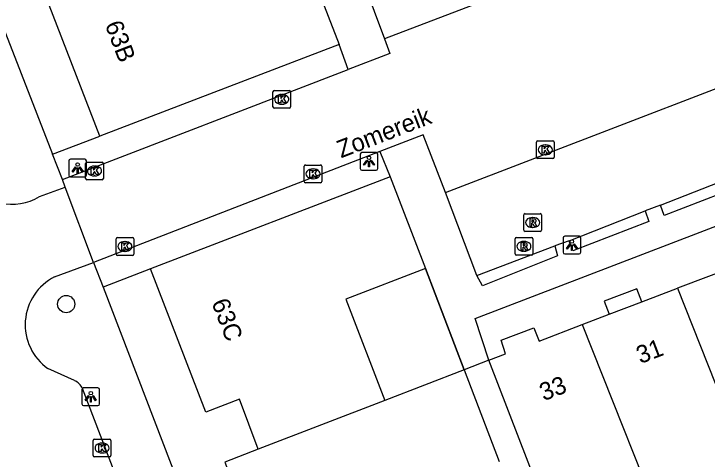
# Model space of a CAD drawing. Extents: x 159265 to 160143, y 383413 to 384319.
# Drawn here: x 159520.52 to 159559.73, y 383650 to 383675.17 of the extents above; entities that cross this region are included whole.
import ezdxf

# ---------------------------------------------------------------- set-up
doc = ezdxf.new("R2010")
doc.units = 0
for name, color, linetype in [('IMGEO_Boom', 7, 'Continuous'), ('IMGEO_Kolk', 7, 'Continuous'), ('IMGEO_Lichtpunt', 7, 'Continuous'), ('IMGEO_Muur', 7, 'Continuous'), ('IMGEO_Openbare_ruimte_label', 7, 'Continuous'), ('IMGEO_Pand', 7, 'Continuous'), ('IMGEO_Pand_nummerreeks', 7, 'Continuous'), ('IMGEO_Pand_overbouw', 7, 'Continuous'), ('IMGEO_Parkeervlak_open', 7, 'Continuous'), ('IMGEO_Rijbaan_lokaal_open', 7, 'Continuous'), ('IMGEO_Rioolput', 7, 'Continuous'), ('IMGEO_Voetpad_open', 7, 'Continuous')]:
    doc.layers.add(name, color=color, linetype=linetype)

msp = doc.modelspace()

# ---------------------------------------------------------------- linework, layer by layer
at = {"layer": 'IMGEO_Boom'}
msp.add_circle((159523.475, 383658.759), 0.489, dxfattribs=at)
at = {"layer": 'IMGEO_Kolk'}
for p, q in [((159535.169, 383669.908), (159535.169, 383670.76)), ((159535.244, 383670.834), (159536.096, 383670.834)), ((159536.17, 383670.76), (159536.17, 383669.908)), ((159535.657, 383670.614), (159535.682, 383670.614)), ((159535.68, 383670.054), (159535.655, 383670.054)), ((159536.096, 383669.834), (159535.244, 383669.834)), ((159550.074, 383667.057), (159550.074, 383667.909)), ((159550.149, 383667.983), (159551.001, 383667.983)), ((159551.075, 383667.909), (159551.075, 383667.057)), ((159550.562, 383667.763), (159550.587, 383667.763)), ((159550.585, 383667.203), (159550.56, 383667.203)), ((159524.576, 383665.857), (159524.576, 383666.709)), ((159524.651, 383666.783), (159525.503, 383666.783)), ((159525.577, 383666.709), (159525.577, 383665.857)), ((159551.001, 383666.983), (159550.149, 383666.983)), ((159525.064, 383666.563), (159525.089, 383666.563)), ((159536.938, 383665.697), (159536.938, 383666.549)), ((159537.013, 383666.623), (159537.865, 383666.623)), ((159537.426, 383666.403), (159537.451, 383666.403)), ((159537.939, 383666.549), (159537.939, 383665.697)), ((159525.087, 383666.003), (159525.062, 383666.003)), ((159525.503, 383665.783), (159524.651, 383665.783)), ((159537.865, 383665.623), (159537.013, 383665.623)), ((159537.449, 383665.843), (159537.424, 383665.843)), ((159526.294, 383661.591), (159526.294, 383662.443)), ((159526.369, 383662.517), (159527.221, 383662.517)), ((159527.295, 383662.443), (159527.295, 383661.591)), ((159526.782, 383662.297), (159526.807, 383662.297)), ((159526.805, 383661.737), (159526.78, 383661.737)), ((159527.221, 383661.517), (159526.369, 383661.517)), ((159525.005, 383650.199), (159525.005, 383651.051)), ((159525.08, 383651.125), (159525.932, 383651.125)), ((159526.006, 383651.051), (159526.006, 383650.199)), ((159525.493, 383650.905), (159525.518, 383650.905)), ((159525.516, 383650.345), (159525.491, 383650.345)), ((159525.932, 383650.125), (159525.08, 383650.125))]:
    msp.add_line(p, q, dxfattribs=at)
for points in [[(159535.169, 383669.908), (159535.169, 383670.76)], [(159535.244, 383670.834), (159536.096, 383670.834)], [(159536.17, 383670.76), (159536.17, 383669.908)], [(159535.49, 383670.534), (159535.613, 383670.534), (159535.613, 383670.383), (159535.743, 383670.534), (159535.907, 383670.534), (159535.761, 383670.383), (159535.914, 383670.134), (159535.762, 383670.134), (159535.677, 383670.298), (159535.613, 383670.231), (159535.613, 383670.134), (159535.49, 383670.134), (159535.49, 383670.534)], [(159536.096, 383669.834), (159535.244, 383669.834)], [(159550.074, 383667.057), (159550.074, 383667.909)], [(159550.149, 383667.983), (159551.001, 383667.983)], [(159551.075, 383667.909), (159551.075, 383667.057)], [(159550.395, 383667.683), (159550.518, 383667.683), (159550.518, 383667.532), (159550.648, 383667.683), (159550.812, 383667.683), (159550.666, 383667.532), (159550.819, 383667.283), (159550.667, 383667.283), (159550.582, 383667.447), (159550.518, 383667.38), (159550.518, 383667.283), (159550.395, 383667.283), (159550.395, 383667.683)], [(159524.576, 383665.857), (159524.576, 383666.709)], [(159524.651, 383666.783), (159525.503, 383666.783)], [(159525.577, 383666.709), (159525.577, 383665.857)], [(159551.001, 383666.983), (159550.149, 383666.983)], [(159524.897, 383666.483), (159525.02, 383666.483), (159525.02, 383666.332), (159525.15, 383666.483), (159525.314, 383666.483), (159525.168, 383666.332), (159525.321, 383666.083), (159525.169, 383666.083), (159525.084, 383666.247), (159525.02, 383666.18), (159525.02, 383666.083), (159524.897, 383666.083), (159524.897, 383666.483)], [(159536.938, 383665.697), (159536.938, 383666.549)], [(159537.013, 383666.623), (159537.865, 383666.623)], [(159537.259, 383666.323), (159537.382, 383666.323), (159537.382, 383666.172), (159537.512, 383666.323), (159537.676, 383666.323), (159537.53, 383666.172), (159537.683, 383665.923), (159537.531, 383665.923), (159537.446, 383666.087), (159537.382, 383666.02), (159537.382, 383665.923), (159537.259, 383665.923), (159537.259, 383666.323)], [(159537.939, 383666.549), (159537.939, 383665.697)], [(159525.503, 383665.783), (159524.651, 383665.783)], [(159537.865, 383665.623), (159537.013, 383665.623)], [(159526.294, 383661.591), (159526.294, 383662.443)], [(159526.369, 383662.517), (159527.221, 383662.517)], [(159527.295, 383662.443), (159527.295, 383661.591)], [(159526.615, 383662.217), (159526.738, 383662.217), (159526.738, 383662.066), (159526.868, 383662.217), (159527.032, 383662.217), (159526.886, 383662.066), (159527.039, 383661.817), (159526.887, 383661.817), (159526.802, 383661.981), (159526.738, 383661.914), (159526.738, 383661.817), (159526.615, 383661.817), (159526.615, 383662.217)], [(159527.221, 383661.517), (159526.369, 383661.517)], [(159525.005, 383650.199), (159525.005, 383651.051)], [(159525.08, 383651.125), (159525.932, 383651.125)], [(159526.006, 383651.051), (159526.006, 383650.199)], [(159525.326, 383650.825), (159525.449, 383650.825), (159525.449, 383650.674), (159525.579, 383650.825), (159525.743, 383650.825), (159525.597, 383650.674), (159525.75, 383650.425), (159525.598, 383650.425), (159525.513, 383650.589), (159525.449, 383650.522), (159525.449, 383650.425), (159525.326, 383650.425), (159525.326, 383650.825)], [(159525.932, 383650.125), (159525.08, 383650.125)]]:
    msp.add_lwpolyline(points, dxfattribs=at)
for centre, start, end in [((159535.246, 383670.758), 91.552, 178.448), ((159535.246, 383670.758), 91.552, 178.448), ((159536.094, 383670.758), 1.552, 88.448), ((159536.094, 383670.758), 1.552, 88.448), ((159535.246, 383669.91), 181.552, 268.448), ((159535.246, 383669.91), 181.552, 268.448), ((159536.094, 383669.91), 271.552, 358.448), ((159536.094, 383669.91), 271.552, 358.448), ((159550.151, 383667.907), 91.552, 178.448), ((159550.151, 383667.907), 91.552, 178.448), ((159550.999, 383667.907), 1.552, 88.448), ((159550.999, 383667.907), 1.552, 88.448), ((159524.653, 383666.707), 91.552, 178.448), ((159524.653, 383666.707), 91.552, 178.448), ((159525.501, 383666.707), 1.552, 88.448), ((159525.501, 383666.707), 1.552, 88.448), ((159550.151, 383667.059), 181.552, 268.448), ((159550.151, 383667.059), 181.552, 268.448), ((159550.999, 383667.059), 271.552, 358.448), ((159550.999, 383667.059), 271.552, 358.448), ((159537.015, 383666.547), 91.552, 178.448), ((159537.015, 383666.547), 91.552, 178.448), ((159537.863, 383666.547), 1.552, 88.448), ((159537.863, 383666.547), 1.552, 88.448), ((159524.653, 383665.859), 181.552, 268.448), ((159524.653, 383665.859), 181.552, 268.448), ((159525.501, 383665.859), 271.552, 358.448), ((159525.501, 383665.859), 271.552, 358.448), ((159537.015, 383665.699), 181.552, 268.448), ((159537.015, 383665.699), 181.552, 268.448), ((159537.863, 383665.699), 271.552, 358.448), ((159537.863, 383665.699), 271.552, 358.448), ((159526.371, 383662.441), 91.552, 178.448), ((159526.371, 383662.441), 91.552, 178.448), ((159527.219, 383662.441), 1.552, 88.448), ((159527.219, 383662.441), 1.552, 88.448), ((159526.371, 383661.593), 181.552, 268.448), ((159526.371, 383661.593), 181.552, 268.448), ((159527.219, 383661.593), 271.552, 358.448), ((159527.219, 383661.593), 271.552, 358.448), ((159525.082, 383651.049), 91.552, 178.448), ((159525.082, 383651.049), 91.552, 178.448), ((159525.93, 383651.049), 1.552, 88.448), ((159525.93, 383651.049), 1.552, 88.448), ((159525.082, 383650.201), 181.552, 268.448), ((159525.082, 383650.201), 181.552, 268.448), ((159525.93, 383650.201), 271.552, 358.448), ((159525.93, 383650.201), 271.552, 358.448)]:
    msp.add_arc(centre, 0.0765, start, end, dxfattribs=at)
for centre, major_axis, ratio, start_param, end_param in [((159535.656, 383670.334), (-0.387, 0.002), 0.722429, 4.712389, 7.853982), ((159535.681, 383670.334), (-0.39, 0.002), 0.717154, 1.570796, 4.712389), ((159550.561, 383667.483), (-0.387, 0.002), 0.722429, 4.712389, 7.853982), ((159550.586, 383667.483), (-0.39, 0.002), 0.717154, 1.570796, 4.712389), ((159525.063, 383666.283), (-0.387, 0.002), 0.722429, 4.712389, 7.853982), ((159525.088, 383666.283), (-0.39, 0.002), 0.717154, 1.570796, 4.712389), ((159537.425, 383666.123), (-0.387, 0.002), 0.722429, 4.712389, 7.853982), ((159537.45, 383666.123), (-0.39, 0.002), 0.717154, 1.570796, 4.712389), ((159526.781, 383662.017), (-0.387, 0.002), 0.722429, 4.712389, 7.853982), ((159526.806, 383662.017), (-0.39, 0.002), 0.717154, 1.570796, 4.712389), ((159525.492, 383650.625), (-0.387, 0.002), 0.722429, 4.712389, 7.853982), ((159525.517, 383650.625), (-0.39, 0.002), 0.717154, 1.570796, 4.712389)]:
    msp.add_ellipse(centre, major_axis=major_axis, ratio=ratio, start_param=start_param, end_param=end_param, dxfattribs=at)
at = {"layer": 'IMGEO_Lichtpunt'}
for p, q in [((159540.104, 383667.233), (159540.104, 383666.426)), ((159540.104, 383667.233), (159540.104, 383666.426)), ((159541.006, 383667.328), (159540.198, 383667.328)), ((159541.006, 383667.328), (159540.198, 383667.328)), ((159541.1, 383666.426), (159541.1, 383667.233)), ((159541.1, 383666.426), (159541.1, 383667.233)), ((159523.621, 383666.851), (159523.621, 383666.044)), ((159523.621, 383666.851), (159523.621, 383666.044)), ((159524.523, 383666.946), (159523.715, 383666.946)), ((159524.523, 383666.946), (159523.715, 383666.946)), ((159524.617, 383666.044), (159524.617, 383666.851)), ((159524.617, 383666.044), (159524.617, 383666.851)), ((159540.198, 383666.332), (159541.006, 383666.332)), ((159540.198, 383666.332), (159541.006, 383666.332)), ((159523.715, 383665.95), (159524.523, 383665.95)), ((159523.715, 383665.95), (159524.523, 383665.95)), ((159551.578, 383662.5), (159551.578, 383661.693)), ((159551.578, 383662.5), (159551.578, 383661.693)), ((159552.48, 383662.595), (159551.672, 383662.595)), ((159552.48, 383662.595), (159551.672, 383662.595)), ((159552.574, 383661.693), (159552.574, 383662.5)), ((159552.574, 383661.693), (159552.574, 383662.5)), ((159551.672, 383661.599), (159552.48, 383661.599)), ((159551.672, 383661.599), (159552.48, 383661.599)), ((159524.369, 383653.925), (159524.369, 383653.118)), ((159524.369, 383653.925), (159524.369, 383653.118)), ((159525.271, 383654.02), (159524.463, 383654.02)), ((159525.271, 383654.02), (159524.463, 383654.02)), ((159525.365, 383653.118), (159525.365, 383653.925)), ((159525.365, 383653.118), (159525.365, 383653.925)), ((159524.463, 383653.024), (159525.271, 383653.024)), ((159524.463, 383653.024), (159525.271, 383653.024))]:
    msp.add_line(p, q, dxfattribs=at)
for points in [[(159540.478, 383666.897), (159540.517, 383666.869), (159540.329, 383666.607), (159540.291, 383666.634), (159540.478, 383666.897)], [(159540.58, 383666.849), (159540.627, 383666.849), (159540.627, 383666.527), (159540.58, 383666.527), (159540.58, 383666.849)], [(159540.69, 383666.869), (159540.728, 383666.896), (159540.915, 383666.634), (159540.876, 383666.606), (159540.69, 383666.869)], [(159523.995, 383666.515), (159524.034, 383666.487), (159523.846, 383666.225), (159523.808, 383666.252), (159523.995, 383666.515)], [(159524.097, 383666.467), (159524.144, 383666.467), (159524.144, 383666.145), (159524.097, 383666.145), (159524.097, 383666.467)], [(159524.207, 383666.487), (159524.245, 383666.514), (159524.432, 383666.252), (159524.393, 383666.224), (159524.207, 383666.487)], [(159551.952, 383662.164), (159551.991, 383662.136), (159551.803, 383661.874), (159551.765, 383661.901), (159551.952, 383662.164)], [(159552.054, 383662.116), (159552.101, 383662.116), (159552.101, 383661.794), (159552.054, 383661.794), (159552.054, 383662.116)], [(159552.164, 383662.136), (159552.202, 383662.163), (159552.389, 383661.901), (159552.35, 383661.873), (159552.164, 383662.136)], [(159524.743, 383653.589), (159524.782, 383653.561), (159524.594, 383653.299), (159524.556, 383653.326), (159524.743, 383653.589)], [(159524.845, 383653.541), (159524.892, 383653.541), (159524.892, 383653.219), (159524.845, 383653.219), (159524.845, 383653.541)], [(159524.955, 383653.561), (159524.993, 383653.588), (159525.18, 383653.326), (159525.141, 383653.298), (159524.955, 383653.561)]]:
    msp.add_lwpolyline(points, dxfattribs=at)
for centre in [(159540.603, 383667.031), (159524.12, 383666.649), (159552.077, 383662.298), (159524.868, 383653.723)]:
    msp.add_circle(centre, 0.0994, dxfattribs=at)
for centre, start, end in [((159540.198, 383667.233), 90, 180), ((159540.198, 383667.233), 90, 180), ((159541.006, 383667.233), 0, 90), ((159541.006, 383667.233), 0, 90), ((159523.715, 383666.851), 90, 180), ((159523.715, 383666.851), 90, 180), ((159524.523, 383666.851), 0, 90), ((159524.523, 383666.851), 0, 90), ((159540.198, 383666.426), 180, 270), ((159540.198, 383666.426), 180, 270), ((159541.006, 383666.426), 270, 0), ((159541.006, 383666.426), 270, 360), ((159523.715, 383666.044), 180, 270), ((159523.715, 383666.044), 180, 270), ((159524.523, 383666.044), 270, 0), ((159524.523, 383666.044), 270, 360), ((159551.672, 383662.5), 90, 180), ((159551.672, 383662.5), 90, 180), ((159552.48, 383662.5), 0, 90), ((159552.48, 383662.5), 0, 90), ((159551.672, 383661.693), 180, 270), ((159551.672, 383661.693), 180, 270), ((159552.48, 383661.693), 270, 0), ((159552.48, 383661.693), 270, 360), ((159524.463, 383653.925), 90, 180), ((159524.463, 383653.925), 90, 180), ((159525.271, 383653.925), 0, 90), ((159525.271, 383653.925), 0, 90), ((159524.463, 383653.118), 180, 270), ((159524.463, 383653.118), 180, 270), ((159525.271, 383653.118), 270, 0), ((159525.271, 383653.118), 270, 360)]:
    msp.add_arc(centre, 0.0946, start, end, dxfattribs=at)
at = {"layer": 'IMGEO_Muur'}
for points in [[(159545.993, 383655.036), (159543.791, 383660.782)], [(159547.388, 383655.597), (159545.993, 383655.036)]]:
    msp.add_lwpolyline(points, dxfattribs=at)
at = {"layer": 'IMGEO_Pand'}
for points in [[(159525.37, 383668.259), (159522.201, 383676.514), (159524.138, 383677.149), (159523.095, 383679.913), (159521.171, 383679.176), (159521.099, 383679.374)], [(159536.923, 383678.599), (159538.916, 383673.44)], [(159538.916, 383673.44), (159525.37, 383668.259)], [(159541.797, 383665.945), (159528.245, 383660.749)], [(159541.797, 383665.945), (159543.791, 383660.782)], [(159563.452, 383661.687), (159558.05, 383659.657)], [(159534.338, 383650.563), (159533.275, 383653.388), (159531.372, 383652.651), (159528.245, 383660.749)], [(159543.791, 383660.782), (159539.298, 383659.043), (159541.492, 383653.311)], [(159552.657, 383657.604), (159554.193, 383658.193), (159556.03, 383658.898), (159558.05, 383659.657)], [(159558.05, 383659.657), (159563.224, 383646.634)], [(159547.388, 383655.597), (159548.329, 383655.948), (159548.07, 383656.719), (159549.92, 383657.428), (159550.219, 383656.668), (159552.657, 383657.604)], [(159552.657, 383657.604), (159557.836, 383644.566)], [(159552.424, 383642.489), (159547.388, 383655.597)], [(159545.993, 383655.036), (159541.492, 383653.311)], [(159545.993, 383655.036), (159547.972, 383649.872)], [(159541.492, 383653.311), (159534.338, 383650.563)], [(159534.338, 383650.563), (159532.448, 383649.829), (159535.549, 383641.791), (159537.45, 383642.531), (159538.535, 383639.636)]]:
    msp.add_lwpolyline(points, dxfattribs=at)
at = {"layer": 'IMGEO_Pand_overbouw'}
msp.add_lwpolyline([(159556.03, 383658.898), (159555.749, 383659.631), (159553.895, 383658.921), (159554.193, 383658.193)], close=True, dxfattribs=at)
at = {"layer": 'IMGEO_Parkeervlak_open'}
for points in [[(159557.088, 383664.345), (159561.377, 383666.032)], [(159551.925, 383662.334), (159556.225, 383664.029)], [(159546.709, 383660.383), (159551.107, 383662.047)]]:
    msp.add_lwpolyline(points, dxfattribs=at)
at = {"layer": 'IMGEO_Rijbaan_lokaal_open'}
for points in [[(159521.968, 383664.836), (159523.427, 383665.372)], [(159525.023, 383661.113), (159523.427, 383665.372)], [(159522.818, 383660.295), (159525.023, 383661.113)], [(159523.945, 383654.433), (159522.443, 383655.121)], [(159535.45, 383625.161), (159524.406, 383653.987)]]:
    msp.add_lwpolyline(points, dxfattribs=at)
for centre, radius, start, end in [((159520.44, 383667.363), 2.953, 212.993, 301.1537), ((159524.179, 383657.596), 3.023, 116.7598, 234.9493), ((159523.551, 383653.564), 0.954, 26.3057, 65.5893)]:
    msp.add_arc(centre, radius, start, end, dxfattribs=at)
at = {"layer": 'IMGEO_Rioolput'}
for p, q in [((159549.358, 383662.946), (159549.358, 383663.798)), ((159549.433, 383663.872), (159550.285, 383663.872)), ((159549.846, 383663.652), (159549.871, 383663.652)), ((159550.359, 383663.798), (159550.359, 383662.946)), ((159550.285, 383662.872), (159549.433, 383662.872)), ((159549.869, 383663.092), (159549.844, 383663.092)), ((159548.861, 383661.6), (159548.861, 383662.452)), ((159548.936, 383662.526), (159549.788, 383662.526)), ((159549.862, 383662.452), (159549.862, 383661.6)), ((159549.349, 383662.306), (159549.374, 383662.306)), ((159549.372, 383661.746), (159549.347, 383661.746)), ((159549.788, 383661.526), (159548.936, 383661.526))]:
    msp.add_line(p, q, dxfattribs=at)
for points in [[(159549.358, 383662.946), (159549.358, 383663.798)], [(159549.433, 383663.872), (159550.285, 383663.872)], [(159549.947, 383663.57), (159549.695, 383663.572), (159549.695, 383663.172)], [(159550.359, 383663.798), (159550.359, 383662.946)], [(159549.695, 383663.172), (159549.819, 383663.172), (159549.819, 383663.334), (159549.83, 383663.334)], [(159549.873, 383663.491), (159549.819, 383663.491), (159549.819, 383663.41)], [(159549.819, 383663.41), (159549.871, 383663.41)], [(159549.877, 383663.305), (159549.948, 383663.172), (159550.088, 383663.172), (159550.023, 383663.298)], [(159550.285, 383662.872), (159549.433, 383662.872)], [(159548.861, 383661.6), (159548.861, 383662.452)], [(159548.936, 383662.526), (159549.788, 383662.526)], [(159549.862, 383662.452), (159549.862, 383661.6)], [(159549.45, 383662.224), (159549.198, 383662.226), (159549.198, 383661.826)], [(159549.376, 383662.145), (159549.322, 383662.145), (159549.322, 383662.064)], [(159549.322, 383662.064), (159549.374, 383662.064)], [(159549.198, 383661.826), (159549.322, 383661.826), (159549.322, 383661.988), (159549.333, 383661.988)], [(159549.38, 383661.959), (159549.451, 383661.826), (159549.591, 383661.826), (159549.526, 383661.952)], [(159549.788, 383661.526), (159548.936, 383661.526)]]:
    msp.add_lwpolyline(points, dxfattribs=at)
for centre, radius, start, end in [((159549.435, 383663.796), 0.0765, 91.552, 178.448), ((159549.435, 383663.796), 0.0765, 91.552, 178.448), ((159549.946, 383663.46), 0.109, 350.3612, 89.416), ((159550.283, 383663.796), 0.0765, 1.552, 88.448), ((159550.283, 383663.796), 0.0765, 1.552, 88.448), ((159549.829, 383663.281), 0.0533, 26.0293, 88.6989), ((159549.855, 383663.599), 0.19, 274.7715, 282.9687), ((159549.879, 383663.395), 0.0964, 77.0061, 93.1865), ((159549.893, 383663.452), 0.0378, 276.6634, 79.6772), ((159549.944, 383663.46), 0.112, 277.5842, 350.9817), ((159549.928, 383663.245), 0.108, 29.5134, 73.7905), ((159549.435, 383662.948), 0.0765, 181.552, 268.448), ((159549.435, 383662.948), 0.0765, 181.552, 268.448), ((159550.283, 383662.948), 0.0765, 271.552, 358.448), ((159550.283, 383662.948), 0.0765, 271.552, 358.448), ((159548.938, 383662.45), 0.0765, 91.552, 178.448), ((159548.938, 383662.45), 0.0765, 91.552, 178.448), ((159549.786, 383662.45), 0.0765, 1.552, 88.448), ((159549.786, 383662.45), 0.0765, 1.552, 88.448), ((159549.358, 383662.253), 0.19, 274.7715, 282.9687), ((159549.382, 383662.049), 0.0964, 77.0061, 93.1865), ((159549.396, 383662.106), 0.0378, 276.6634, 79.6772), ((159549.449, 383662.114), 0.109, 350.3612, 89.416), ((159549.447, 383662.114), 0.112, 277.5842, 350.9817), ((159549.431, 383661.899), 0.108, 29.5134, 73.7905), ((159549.332, 383661.935), 0.0533, 26.0293, 88.6989), ((159548.938, 383661.602), 0.0765, 181.552, 268.448), ((159548.938, 383661.602), 0.0765, 181.552, 268.448), ((159549.786, 383661.602), 0.0765, 271.552, 358.448), ((159549.786, 383661.602), 0.0765, 271.552, 358.448)]:
    msp.add_arc(centre, radius, start, end, dxfattribs=at)
for centre, major_axis, ratio, start_param, end_param in [((159549.845, 383663.372), (-0.387, 0.002), 0.722429, 4.712389, 7.853982), ((159549.87, 383663.372), (-0.39, 0.002), 0.717154, 1.570796, 4.712389), ((159549.348, 383662.026), (-0.387, 0.002), 0.722429, 4.712389, 7.853982), ((159549.373, 383662.026), (-0.39, 0.002), 0.717154, 1.570796, 4.712389)]:
    msp.add_ellipse(centre, major_axis=major_axis, ratio=ratio, start_param=start_param, end_param=end_param, dxfattribs=at)
at = {"layer": 'IMGEO_Voetpad_open'}
for points in [[(159509.321, 383701.658), (159512.811, 383692.674), (159522.704, 383667.239)], [(159566.604, 383683.353), (159541.475, 383673.747)], [(159539.729, 383678.468), (159541.475, 383673.747)], [(159544.922, 383665.063), (159569.95, 383674.669)], [(159547.388, 383655.597), (159546.608, 383657.945), (159589.409, 383674.359)], [(159539.421, 383672.017), (159538.916, 383673.44)], [(159541.475, 383673.747), (159541.779, 383672.925), (159539.421, 383672.017)], [(159523.264, 383665.799), (159539.421, 383672.017)], [(159544.922, 383665.063), (159543.674, 383668.329), (159541.223, 383667.381)], [(159522.704, 383667.239), (159525.37, 383668.259)], [(159523.264, 383665.799), (159522.704, 383667.239)], [(159541.223, 383667.381), (159525.023, 383661.113)], [(159541.223, 383667.381), (159541.797, 383665.945)], [(159561.377, 383666.032), (159561.586, 383665.433), (159557.297, 383663.769), (159557.088, 383664.345)], [(159523.427, 383665.372), (159523.264, 383665.799)], [(159546.709, 383660.383), (159544.922, 383665.063)], [(159556.225, 383664.029), (159556.426, 383663.431), (159552.135, 383661.777), (159551.925, 383662.334)], [(159557.088, 383664.345), (159556.225, 383664.029)], [(159551.107, 383662.047), (159551.262, 383661.484), (159547.016, 383659.79), (159546.709, 383660.383)], [(159551.925, 383662.334), (159551.107, 383662.047)], [(159525.023, 383661.113), (159525.558, 383659.719)], [(159528.245, 383660.749), (159525.558, 383659.719)], [(159543.791, 383660.782), (159545.993, 383655.036)], [(159525.558, 383659.719), (159539.547, 383623.252), (159557.382, 383576.165)], [(159547.388, 383655.597), (159545.993, 383655.036)]]:
    msp.add_lwpolyline(points, dxfattribs=at)

# ---------------------------------------------------------------- texts
at = {"layer": 'IMGEO_Openbare_ruimte_label'}
msp.add_text('Zomereik', height=1, rotation=21.0457, dxfattribs=at).set_placement((159539.02, 383666.999))
at = {"layer": 'IMGEO_Pand_nummerreeks'}
for s, rotation, p in [('63B', 290.9996, (159525.652, 383674.556)), ('63C', 291.1151, (159531.68, 383658.85)), ('31', 20.9793, (159555.951, 383655.368)), ('33', 20.9793, (159550.478, 383653.269))]:
    msp.add_text(s, height=1, rotation=rotation, dxfattribs=at).set_placement(p)

doc.saveas('drawing.dxf')
